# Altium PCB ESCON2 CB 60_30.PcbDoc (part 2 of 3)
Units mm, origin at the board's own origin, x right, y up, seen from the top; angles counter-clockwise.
Board outline 93.5 x 46 mm, 8 copper layers (Top Side, Inner Layer 1, Inner Layer 2, Inner Layer 3, Inner Layer 4, Inner Layer 5, Inner Layer 6, Bottom Side), stack 1.485 mm thick; 144 components, 77 nets, 473 pads, 3049 vias.
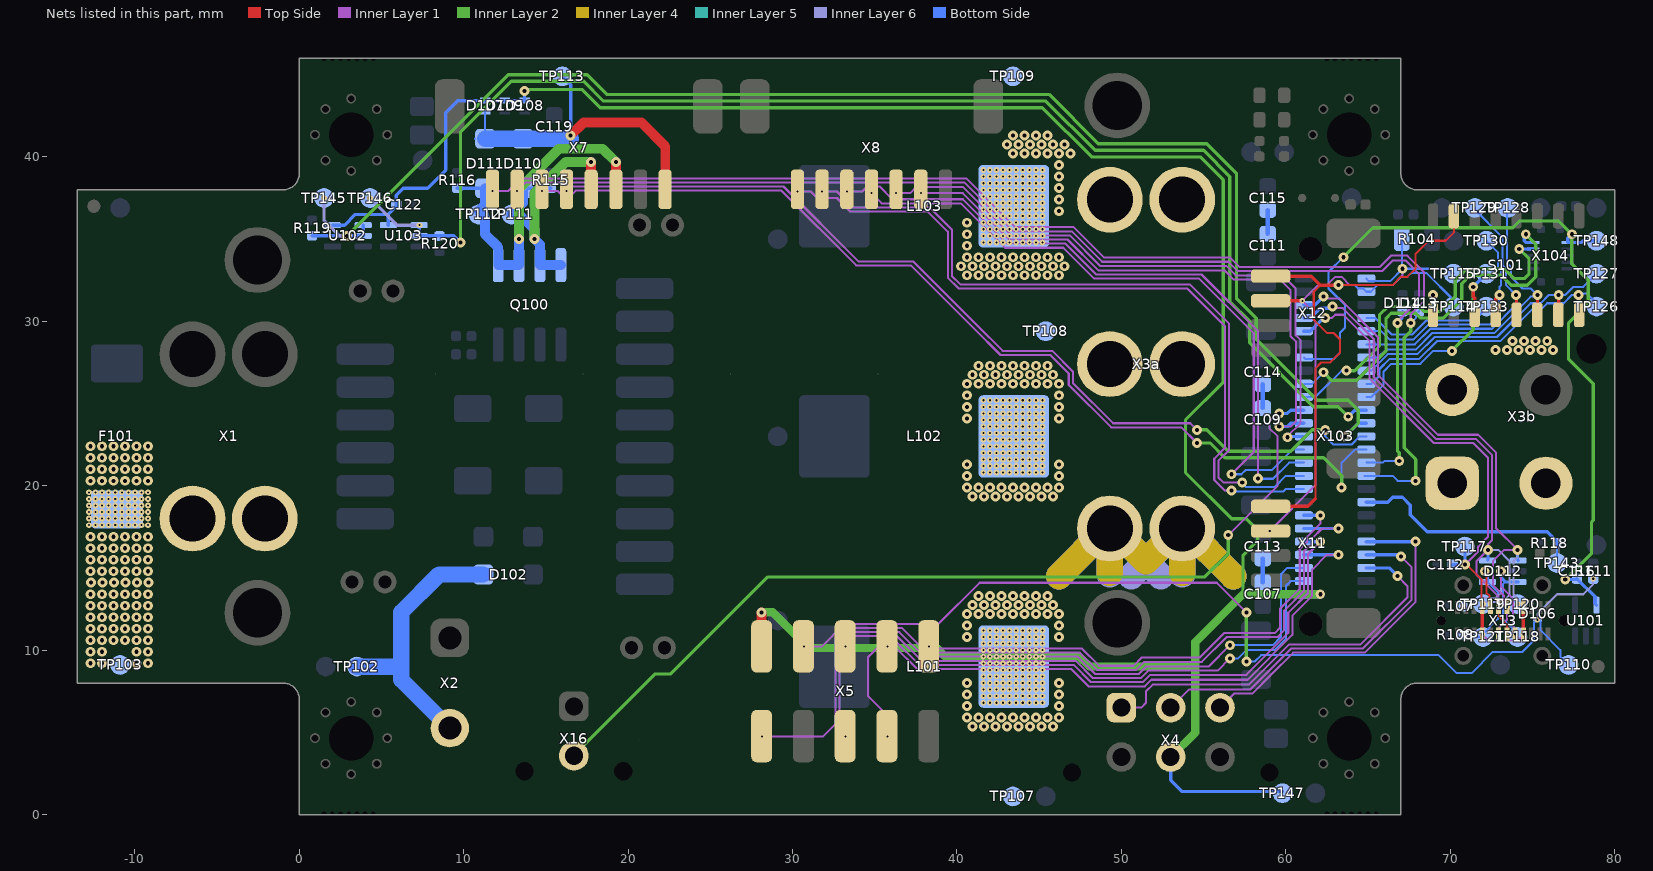
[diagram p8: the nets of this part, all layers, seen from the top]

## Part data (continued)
D112: library part CMP-000635-10, "Transient Voltage Suppressor Diode, 4-Line, 5V V(RWM), Unidirectional, 30W, 4 Element , SOT353/SC-88A", Breakdown Voltage=6.8V, Case="SOT353; SC-88A; SOT323-5L", Clamping Voltage=12V, Manufacturer=Nexperia, Max Breakdown Voltage=7.14V, Max Junction Temperature=150°C, Min Breakdown Voltage=6.46V, Min Operating Temperature=-65°C
D113 D114: library part CMP-000066-17, "Transient Voltage Suppressor Diode, 30V V(RWM), Bidirectional, ESD, 1 Element, 0402", Breakdown Voltage=30V, Case=0402, Manufacturer=Panasonic, Max Operating Temperature=125°C, Min Operating Temperature=-55°C
DS101: library part CMP-000723-6, "Single Color Chip LED, red, 0603", Case=0603, Color(s)=Red, Manufacturer=Dialight, Max Operating Temperature=100°C, Min Operating Temperature=-40°C
DS102: library part CMP-000722-5, "Single Color Chip LED, green, 0603", Case=0603, Color(s)=Green, Manufacturer=Dialight, Max Operating Temperature=100°C, Min Operating Temperature=-40°C
F101: library part CMP-001105-4, "Electric Fuse, Fast Acting, 40A, 72VDC, Surface Mount", Case=0456, Current Rating=40A, Manufacturer=BelFuse, Max Operating Temperature=125°C, Maximum Working Voltage=72V, Min Operating Temperature=-55°C
FD101 FD102 FD103 FD104: library part CMP-000010-5, "Fiducial, Global, Round; 0.80 mm D, 1.60 mm Clearance"
L101 L102 L103: library part CMP-001104-3, "Inductor Shielded, 0.47uH, 20%, I_RMS>34A, I_Sat>58A, R<1.3mOhm, 13.0x14.0mm, Height<=5mm", DC Resistance=1.3m, Max Operating Temperature=125°C, Min Operating Temperature=-55°C, RMS Current=34A, Saturation Current=58A, Tolerance=20%
LS101: library part CMP-001088-3, "Layer Stair 8 Layer"
MH101 MH102 MH103 MH104: library part CMP-000029-10, "Mounting Hole, Non-Plated; 5.50 mm Clearance, 2.70 mm Hole (with 8 vias)"
Q100: library part CMP-001108-5, "N-Channel MOSFET, Self Protected, 36V, 0.5ohm, SO-8", Case="SO-8, SOIC-8, PG-DSO-8", Drain Source Voltage=36V, Manufacturer="ST Microelectronics", Max Operating Temperature=150°C, Min Operating Temperature=-55°C
R102 R103 R105: library part CMP-000398-10, "47R 1% 250mW 100ppm", Case=1206, Case (Metric)=3216, Manufacturer=X, Max Junction Temperature=155°C, Maximum Overload Voltage=400V, Maximum Working Voltage=200V, Min Operating Temperature=-55°C, Part Number="Thick-Film, 1206, 47, 1%, 250mW@70°C, 200V, 100ppm, -55°C to 155°C", Power Rating=250mW, Power Rating Temperature=70°C, Temperature Coefficient=100ppm, Tolerance=1%
R104: library part CMP-000325-10, "120R 1% 125mW 100ppm", Case=0805, Case (Metric)=2012, Manufacturer=X, Max Junction Temperature=155°C, Maximum Overload Voltage=300V, Maximum Working Voltage=150V, Min Operating Temperature=-55°C, Part Number="Thick-Film, 0805, 120, 1%, 125mW@70°C, 150V, 100ppm, -55°C to 155°C", Power Rating=125mW, Power Rating Temperature=70°C, Temperature Coefficient=100ppm, Tolerance=1%
R107 R108: library part CMP-000206-11, "5.1k 1% 62.5mW 100ppm", Case=0402, Case (Metric)=1050, Manufacturer=X, Max Junction Temperature=155°C, Maximum Overload Voltage=100V, Maximum Working Voltage=50V, Min Operating Temperature=-55°C, Part Number="Thick-Film, 0402, 5.1k, 1%, 62.5mW@70°C, 50V, 100ppm, -55°C to 155°C", Power Rating=62.5mW, Power Rating Temperature=70°C, Temperature Coefficient=100ppm, Tolerance=1%
R109 R110: library part CMP-000185-11, "680R 1% 62.5mW 100ppm", Case=0402, Case (Metric)=1050, Manufacturer=X, Max Junction Temperature=155°C, Maximum Overload Voltage=100V, Maximum Working Voltage=50V, Min Operating Temperature=-55°C, Part Number="Thick-Film, 0402, 680, 1%, 62.5mW@70°C, 50V, 100ppm, -55°C to 155°C", Power Rating=62.5mW, Power Rating Temperature=70°C, Temperature Coefficient=100ppm, Tolerance=1%
R111: library part CMP-000161-11, "47R 1% 62.5mW 100ppm", Case=0402, Case (Metric)=1050, Manufacturer=X, Max Junction Temperature=155°C, Maximum Overload Voltage=100V, Maximum Working Voltage=50V, Min Operating Temperature=-55°C, Part Number="Thick-Film, 0402, 47, 1%, 62.5mW@70°C, 50V, 100ppm, -55°C to 155°C", Power Rating=62.5mW, Power Rating Temperature=70°C, Temperature Coefficient=100ppm, Tolerance=1%
R112 R114: library part CMP-000173-11, "220R 1% 62.5mW 100ppm", Case=0402, Case (Metric)=1050, Manufacturer=X, Max Junction Temperature=155°C, Maximum Overload Voltage=100V, Maximum Working Voltage=50V, Min Operating Temperature=-55°C, Part Number="Thick-Film, 0402, 220, 1%, 62.5mW@70°C, 50V, 100ppm, -55°C to 155°C", Power Rating=62.5mW, Power Rating Temperature=70°C, Temperature Coefficient=100ppm, Tolerance=1%
R115 R116: library part CMP-000197-11, "2.2k 1% 62.5mW 100ppm", Case=0402, Case (Metric)=1050, Manufacturer=X, Max Junction Temperature=155°C, Maximum Overload Voltage=100V, Maximum Working Voltage=50V, Min Operating Temperature=-55°C, Part Number="Thick-Film, 0402, 2.2k, 1%, 62.5mW@70°C, 50V, 100ppm, -55°C to 155°C", Power Rating=62.5mW, Power Rating Temperature=70°C, Temperature Coefficient=100ppm, Tolerance=1%
R117: library part CMP-000466-10, "0R Jumper", Case=0402, Case (Metric)=1050, Manufacturer=X, Max Junction Temperature=155°C, Maximum Overload Voltage=100V, Maximum Working Voltage=50V, Min Operating Temperature=-55°C, Part Number="Thick-Film, 0402, 0, -55°C to 155°C", RMS Current=1A
R118 R119 R120 R121: library part CMP-000492-11, "10k 1% 62.5mW 100ppm", Case=0402, Case (Metric)=1050, Manufacturer=X, Max Junction Temperature=155°C, Maximum Overload Voltage=100V, Maximum Working Voltage=50V, Min Operating Temperature=-55°C, Part Number="Thick-Film, 0402, 10k, 1%, 62.5mW@70°C, 50V, 100ppm, -55°C to 155°C", Power Rating=62.5mW, Power Rating Temperature=70°C, Temperature Coefficient=100ppm, Tolerance=1%
S101: library part CMP-001031-3, "Slide Dip Switch, 8 Switches, 0.025A, 24VDC, SMD", Manufacturer=Diptronics, Max Operating Temperature=85°C, Min Operating Temperature=-40°C
STEG101 STEG102 STEG103 STEG104: library part CMP-000007-5, "Breakaway tabs; 4.00 mm L X 0.90 mm W, 7 Hole"
SYM101: library part CMP-000019-5, "ESD-Sign; 2.5 mm L X 2.25 mm W"
SYM702: library part CMP-001187-11, "Barcode EMS; 4.1 x 4.1 mm"
TP101 TP102 TP103 TP104 TP106 TP107 TP108 TP109 TP110 TP111 TP112 TP113 TP114 TP115 TP116 TP117 TP118 TP119 TP120 TP121 TP125 TP126 TP127 TP128 TP129 TP130 TP131 TP132 TP133 TP134 TP138 TP139 TP140 TP141 TP142 TP143 TP144 TP145 TP146 TP147 TP148 TP149 TP153 TP154 TP155: library part CMP-000014-7, "Test Point; 1 pin, 1.20 mm D"
TPM1 TPM2: library part CMP-001150-4, "Test point measure; 1 pin, 0.50 mm D"
U101: library part CMP-001041-6, "Single buffer with Schmitt-Trigger inputs", Case="5-TSSOP, SC-70-5, SOT-353", Manufacturer="Texas Instruments", Max Operating Temperature=125°C, Max Storage Temperature=150°C, Max Supply Voltage=5.5V, Min Operating Temperature=-40°C, Min Storage Temperature=-65°C, Min Supply Voltage=1.65V
U102 U103: library part CMP-002037-1, "Single, 2-Input NAND Gate, 5V", Case="SC-88A , SC-70-5, SOT353-1", Max Operating Temperature=125°C, Max Supply Voltage=5.5V, Min Operating Temperature=-40°C, Min Supply Voltage=4.5V
X1: library part CMP-001093-5, "10.00mm Pitch Mini-Fit Sr. Header, Single Row, Vertical, 1.57mm PCB Thickness, 2 Circuits", Manufacturer=Molex, Max Operating Temperature=105°C, Min Operating Temperature=-40°C, Operating Current=50A, Operating Voltage=600V
X2: library part CMP-001018-5, "Mini-Fit Jr. Vertical Header, 4.20mm Pitch, Dual Row, 2 Circuits, without Snap-in Plastic Peg PCB Lock, Tin, Natural", Manufacturer=Molex, Max Operating Temperature=105°C, Min Operating Temperature=-40°C, Operating Current=9A, Operating Voltage=600V
X3a: library part CMP-001094-4, "10.00mm Pitch Mini-Fit Sr. Header, Single Row, Vertical, 1.57mm PCB Thickness, 3 Circuits", Manufacturer=Molex, Max Operating Temperature=105°C, Min Operating Temperature=-40°C, Operating Current=50A, Operating Voltage=600V
X3b: library part CMP-001095-4, "Mega-Fit Slim Vertical Header, Through Hole, 5.70mm Pitch, Dual Row, 4 Circuits, Black", Manufacturer=Molex, Max Operating Temperature=120°C, Min Operating Temperature=-40°C, Operating Current=23.5A, Operating Voltage=600V
X4: library part CMP-001098-6, "Micro-Fit 3.0 Vertical Header, 3.00mm Pitch, Dual Row, 6 Circuits, with PCB Polarizing Peg, Black", Manufacturer=Molex, Max Operating Temperature=105°C, Min Operating Temperature=-40°C, Operating Current=8.5A, Operating Voltage=600V
X5: library part CMP-001165-3, "Header, 2.54mm Pitch, Dual Row, SMT, Vertical, 10 Circuits", Manufacturer=Amphenol, Max Operating Temperature=125°C, Min Operating Temperature=-65°C, Operating Current=3A, Operating Voltage=500V
X7: library part CMP-001014-7, "1.50mm Pitch, CLIK-Mate PCB Receptacle, Single Row, Surface Mount, Tin Plating, Positive Lock, with Pick-and-Place Polyimide Tape, 8 Circuits, Beige", Manufacturer=Molex, Max Operating Temperature=105°C, Min Operating Temperature=-40°C, Operating Current=2A, Operating Voltage=100V
X8: library part CMP-001015-7, "1.50mm Pitch, CLIK-Mate PCB Receptacle, Single Row, Surface Mount, Tin Plating, Positive Lock, with Pick-and-Place Polyimide Tape, 7 Circuits, Beige", Manufacturer=Molex, Max Operating Temperature=105°C, Min Operating Temperature=-40°C, Operating Current=2A, Operating Voltage=100V
X11 X12: library part CMP-001170-6, "1.50mm Pitch, CLIK-Mate PCB Receptacle, Single Row, Surface Mount, Tin Plating, Positive Lock, with Pick-and-Place Polyimide Tape, 4 Circuits, Beige", Manufacturer=Molex, Max Operating Temperature=105°C, Min Operating Temperature=-40°C, Operating Current=2A, Operating Voltage=100V
X13: library part CMP-001110-9, "USB Type C, SHLD, 24poles, vertical", Manufacturer=GTC, Max Operating Temperature=85°C, Min Operating Temperature=-25°C
X16: library part CMP-001107-4, "Micro-Fit 3.0 Vertical Header, 3.00mm Pitch, Dual Row, 2 Circuits, with PCB Polarizing Peg, Black", Manufacturer=Molex, Max Operating Temperature=105°C, Min Operating Temperature=-40°C, Operating Current=8.5A, Operating Voltage=600V
X101: library part CMP-001100-9, "2.00 mm mPOWER® Ultramikro-Power-Socket, 6-polig", Manufacturer=Samtec, Max Operating Temperature=125°C, Min Operating Temperature=-55°C, Operating Current=18A, Operating Voltage=460V
X102: library part CMP-001189-6, "2.00 mm mPOWER® Ultramikro-Power-Socket, 10-polig", Manufacturer=Samtec, Max Operating Temperature=125°C, Min Operating Temperature=-55°C, Operating Current=18A, Operating Voltage=460V
X103: library part CMP-001102-8, "0.80 mm Edge Rate® Rugged High Speed Terminal", Max Operating Temperature=125°C, Min Operating Temperature=-55°C, Operating Current=1.4A, Operating Voltage=225V
X104: library part CMP-001083-11, "Board to Board Connector, 2*5 pole, SMD, 0.4mm pitch, 1.5mm stacking Height", Manufacturer=Panasonic, Max Operating Temperature=85°C, Min Operating Temperature=-55°C, Operating Current=300mA, Operating Voltage=60V

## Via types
v1: diameter 0.35, hole 0.125, Inner Layer 6 to Bottom Side, tented both sides, 1246 vias
v2: diameter 0.6, hole 0.25, Top Side to Bottom Side, 953 vias
v3: diameter 0.35, hole 0.125, Top Side to Inner Layer 1, tented both sides, 790 vias
v4: diameter 0.6, hole 0.25, Top Side to Bottom Side, tented bottom, 58 vias
v5: diameter 0.6, hole 0.25, Top Side to Bottom Side, tented top, 2 vias

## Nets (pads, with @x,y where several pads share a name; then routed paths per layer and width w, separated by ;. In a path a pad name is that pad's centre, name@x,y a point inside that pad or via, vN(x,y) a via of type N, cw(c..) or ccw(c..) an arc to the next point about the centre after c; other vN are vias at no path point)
3V3: C116.2 TP148.1 U101.5 X103.38 X104.1 | length 52.8
  Inner Layer 2 w0.2: v2(63.5,33.9) 65.3,35.7 73.8,35.7 74.2,36.1 76.6,36.1 v2(77.4,35.3) 77.4,33.5 78.4,32.5 78.4,31.1 77.2,29.9 77.2,27.7 78.7,26.2 78.7,17.9 78.6,17.8 78.6,15.9 v2(77,14.3)
  Bottom Side w0.125: X103.38@61.1,27.8 61.2,27.7 62.9,27.7 63.3,28.1 63.3,29.3 63.6,29.6 63.6,31 62.6,32 62.6,33 v2(63.5,33.9)
  Bottom Side w0.2: v2(77,14.3) 77.7,14.3 C116.2@77.7,14.35 78.815,13.235 78.815,12.82 U101.5@78.9,12.735 ; v2(77.4,35.3) 77.145,35.045 X104.1@77.145,34.8 78,34.8 78.1,34.9 TP148.1@78.9,34.9
5V0_sensor1_2: C122.2 D107.2 D108.2 D109.2 TP147.1 U102.5 U103.5 X4.5 X5.2 X103.2 | length 148
  Top Side w0.6: v2(28.1,12.3) 28.1,11.84 28.12,11.82 X5.2@28.12,10.23
  Inner Layer 2 w0.2: v2(13.7,44) 13.8,44.1 17.2,44.1 18.3,43 45.2,43 48.2,40 54.8,40 56.2,38.6 56.2,26.3 53.9,24 53.9,20.8 56.7,18 57.6,18 58.3,17.3 58.3,16.675 57.4,15.775 57.4,13.4
  Inner Layer 2 w0.5: v2(28.1,12.3) 28.8,12.3 30.975,10.125 38.775,10.125 39.275,9.625 47.425,9.625 48.05,9 54.497,9 ; X4.5@53,3.5 54.497,4.997 54.497,9 ; v2(62.1,13.4) 57.4,13.4 54.497,10.497 54.497,9
  Bottom Side w0.2: U102.5@2.015,35.85 2.75,35.85 3.4,36.5 5.415,36.5 ; U103.5@5.415,35.85 5.415,36.5 ; v2(13.7,44) D108.2@13.7,43.425 D109.2@12.5,43.425 D107.2@11.3,43.425 9.625,43.425 8.9,42.7 8.9,39.2 7.8,38.1 6.325,38.1 5.9,37.675 C122.2@5.9,37.1 5.9,36.985 5.415,36.5 ; X4.5@53,3.5 53,2.1 53.7,1.4 TP147.1@59.8,1.4
  Bottom Side w0.5: X103.2@61.1,13.4 v2(62.1,13.4)
C_ADC_CB_Ident: R118.2 TP143.1 X103.15 | length 14.5
  Bottom Side w0.125: TP143.1@76.5,15.3 R118.2@76.5,16.4
  Bottom Side w0.2: X103.15@64.9,19 66.2,19 66.5,19.3 67.1,19.3 67.575,18.825 67.575,18.225 68.6,17.2 75.9,17.2 76.5,16.6 R118.2@76.5,16.4
C_AnIN1+: X8.1 X103.18 | length 46.5
  Inner Layer 1 w0.125: v3(30.3,37.9) 31.1,37.9 31.5,37.5 32.7,37.5 33.525,36.675 38.225,36.675 39.45,35.45 39.45,32.65 40.1,32 54,32 56.3,29.7 56.3,22.3 55.65,21.65 55.65,20.35 56.3,19.7 v2(56.7,19.7)
  Bottom Side w0.125: v2(56.7,19.7) 56.75,19.65 59.85,19.65 60,19.8 X103.18@61.1,19.8
C_AnIN1-: X8.2 X103.20 | length 45.1
  Inner Layer 1 w0.125: v3(31.8,37.9) 32.7,37.9 33.675,36.925 38.35,36.925 39.7,35.575 39.7,32.754 40.204,32.25 54.15,32.25 56.55,29.85 56.55,22.175 55.9,21.525 55.9,20.5 56.2,20.2 v2@57.3,20.2
  Bottom Side w0.125: v2@57.3,20.2 57.575,19.925 59.325,19.925 60,20.6 X103.20@61.1,20.6
  other v2: 57.35,20.2
C_AnIN2+: X8.3 X103.22 | length 40.9
  Inner Layer 1 w0.125: v3(33.3,37.9) 34.25,37.9 34.55,38.2 35.3,38.2 36.075,37.425 40.35,37.425 43.05,34.725 46.6,34.725 48.475,32.85 54.875,32.85 58.3,29.425 v2(58.3,20.45)
  Bottom Side w0.125: v2(58.3,20.45) 58.325,20.425 59.225,20.425 60.2,21.4 X103.22@61.1,21.4
C_AnIN2-: X8.4 X103.24 | length 41
  Inner Layer 1 w0.125: v3(34.8,37.8) 35.425,37.175 40.225,37.175 42.925,34.475 46.475,34.475 48.35,32.6 54.725,32.6 58.05,29.275 58.05,22.05 v2@56.668,20.668
  Bottom Side w0.125: v2(56.7,20.7) 57.3,20.7 57.55,20.95 59.15,20.95 60.4,22.2 X103.24@61.1,22.2
C_AnOUT1: X8.5 X103.26 | length 37.5
  Inner Layer 1 w0.125: v3(36.3,37.8) 37.15,37.8 37.525,38.175 40.35,38.175 43.3,35.225 46.85,35.225 48.7,33.375 56.375,33.375 56.95,32.8 59.8,32.8 60.6,32 60.6,31.1 60.6,29.15 60.9,28.85 60.9,23.8 v2@60.1,23
  Bottom Side w0.2: v2@60.1,23 60.55,23 X103.26@61.1,23
  other v2: 60.1,22.95
C_AnOUT2: X8.6 X103.28 | length 35.8
  Inner Layer 1 w0.125: v3(37.8,37.8) 40.35,37.8 43.175,34.975 46.725,34.975 48.6,33.1 56.275,33.1 56.838,32.538 59.662,32.538 60.3,31.9 60.3,31 60.3,29.075 60.625,28.75 60.625,23.925 60.3,23.6 v2(59.6,23.6)
  Bottom Side w0.2: v2(59.6,23.6) 60.1,23.6 60.3,23.8 X103.28@61.1,23.8
C_CANH: S101.7 TP114.1 X11.1 X12.1 X103.47 | length 40.9
  Top Side w0.125: 61.8,19.2 61.8,27.125 62.175,27.5 62.7,27.5 63.3,28.1 63.3,28.9 62.9,29.3 62.5,29.3 61.7,30.1 61.7,31.8 62.1,32.2 ; v2(63.2,32.2) 64.2,32.2 65.375,32.2 66.5,32.2 67,32.7 67.4,32.7 67.9,33.2 67.9,34.1 68.7,34.9 69.725,34.9 70.225,35.4 S101.7@70.225,36.407
  Top Side w0.2: X11.1@59.025,18.75 61.35,18.75 61.8,19.2 ; X12.1@59.075,32.75 61.55,32.75 62.1,32.2 v2(63.2,32.2)
  Bottom Side w0.125: v2(63.2,32.2) 64.2,32.2 64.4,32 64.7,32 X103.47@64.9,31.8 65.175,31.8 65.575,32.2 66.5,32.2 67,32.7 67.4,32.7 67.65,32.95 68.55,32.95 70.2,31.3 TP114.1@70.2,30.9
C_CANL: R104.2 TP115.1 X11.2 X12.2 X103.49 | length 32.6
  Top Side w0.2: X12.2@59.025,31.25 X12.2@59.075,31.25 v3@61.004,31.25
  Inner Layer 1 w0.125: v3(59.025,17.25) 61.8,20.025 61.8,30 61.7,30.1 61.7,30.554 v3(61.005,31.249) 61.915,32.16 62.46,32.16 63,32.7 63.4,32.7 63.9,32.2 66.5,32.2 67.1,32.8 v2(67.1,33.2)
  Bottom Side w0.125: X103.49@64.9,32.6 65.05,32.45 66.35,32.45 v2(67.1,33.2) 69.9,33.2 TP115.1@70.2,32.9 ; v2@67.075,33.225 R104.2@67.075,35
C_DigIN1: D113.2 X7.1 X103.19 | length 77.5
  Inner Layer 1 w0.125: v3(11.75,37.925) 12.7,37.925 13.475,38.7 40.575,38.7 43.55,35.725 47.1,35.725 48.95,33.875 56.625,33.875 57.2,33.3 65.7,33.3 66.4,34 67.4,34 68.4,33 68.4,31.225 67.6,30.425 v2(67.6,29.9)
  Inner Layer 2 w0.2: v2(67.6,29.9) 67.6,29.4 67.2,29 67.2,22.3 67.9,21.6 v2(67.9,20.3)
  Bottom Side w0.125: X103.19@64.8,20.6 66.5,20.6 66.8,20.3 v2(67.9,20.3) ; v2(67.6,29.9) 67.927,30.227 67.927,30.442 D113.2@68.1,30.615
C_DigIN2: D114.2 X7.2 X103.21 | length 72.8
  Inner Layer 1 w0.125: v3(13.25,37.925) 13.775,38.45 40.45,38.45 43.425,35.475 46.975,35.475 48.825,33.625 56.5,33.625 57.075,33.05 65.85,33.05 66.5,33.7 67.3,33.7 68.1,32.9 68.1,31.3 v2@66.7,29.9
  Inner Layer 2 w0.2: v2(66.8,29.9) 66.8,22.1 66.9,22 v2(66.9,21.5)
  Bottom Side w0.125: X103.21@64.9,21.4 65.9,21.4 66,21.5 v2(66.9,21.5) ; v2(66.8,29.9) 67.1,30.2 D114.2@67.1,30.615
C_DigIN3: X7.3 X103.23 | length 60.6
  Inner Layer 1 w0.125: v3(14.75,37.925) 15.725,37.925 16.1,37.55 16.4,37.55 16.8,37.95 29.325,37.95 33.875,33.4 37.2,33.4 41,29.6 42.65,27.95 45.675,27.95 46.8,26.825 46.8,26.125 49.375,23.55 53.65,23.55 v2(54.6,22.6)
  Inner Layer 2 w0.2: v2(54.6,22.6) 55.4,22.6 56.3,21.7 62.3,21.7 63.4,20.6 v2(63.4,19.9)
  Bottom Side w0.125: v2(63.4,19.9) 63.4,21.4 64.2,22.2 X103.23@64.9,22.2
C_DigIN4: X7.4 X103.25 | length 57.2
  Inner Layer 1 w0.125: v3(16.25,37.925) 16.525,38.2 29.45,38.2 34,33.65 37.325,33.65 41.25,29.725 42.775,28.2 45.8,28.2 47.05,26.95 47.05,26.25 49.5,23.8 54.2,23.8 v2(54.6,23.4)
  Inner Layer 2 w0.2: v2(54.6,23.4) 55.2,23.4 56.5,22.1 60.3,22.1 61.6,23.4 v2(62.4,23.4)
  Bottom Side w0.125: v2(62.4,23.4) 62.4,23 62.9,22.5 64,22.5 64.5,23 X103.25@64.9,23
C_DigOUT1: D110.2 Q100.7 Q100.8 R115.1 TP111.1 X7.5 | length 17.3
  Top Side w0.6: X7.5@17.75,37.925 v2@17.75,39.6
  Inner Layer 2 w0.6: v2(14.3,35) 14.3,37.8 16.2,39.7 v2(17.75,39.7)
  Bottom Side w0.2: D110.2@13.6,38.095 14.205,38.095 14.21,38.1 R115.1@15.3,38.1
  Bottom Side w0.6: TP111.1@12.9,36.5 13.6,37.2 D110.2@13.6,38.095 ; TP111.1@13.3,36.6 14.3,35.6 v2(14.3,35) 14.635,34.665 Q100.7@14.635,33.42 Q100.8@15.905,33.42
C_DigOUT2: D111.2 Q100.5 Q100.6 R116.1 TP112.1 X7.6 | length 22.2
  Top Side w0.6: X7.6@19.25,37.925 v2@19.25,39.6
  Inner Layer 2 w0.6: v2(13.35,35) 13.35,38.05 15.8,40.5 18.45,40.5 v2(19.25,39.7)
  Bottom Side w0.2: R116.1@9.6,38.1 10.69,38.1 10.695,38.095 D111.2@11.3,38.095
  Bottom Side w0.6: TP112.1@11.205,36.7 TP112.1@10.9,36.7 ; D111.2@11.3,38.095 11.3,37.1 TP112.1@10.9,36.7 ; v2(13.35,35) 13.365,34.985 Q100.6@13.365,33.42 Q100.5@12.095,33.42 12.095,34.505 11.3,35.3 11.3,36.3 TP112.1@10.9,36.7
C_MotorTemp: X16.2 X103.30 | length 56.7
  Inner Layer 1 w0.125: v2(56.5,17) 59.5,20 59.5,23 59,23.5 59,23.9 59.5,24.4 v2(59.6,24.4)
  Inner Layer 2 w0.2: X16.2@16.7,3.6 21.65,8.55 22.6,8.55 28.5,14.45 55.075,14.45 56.5,15.875 v2(56.5,17)
  Bottom Side w0.2: v2(59.6,24.4) 60.1,24.4 60.3,24.6 X103.30@61.1,24.6
C_S1_Hall1: X4.1 X103.5 | length 24.2
  Inner Layer 1 w0.125: X4.1@50,6.5 51.2,6.5 51.5,6.8 51.5,7.5 51.9,7.9 57.75,7.9 60.2,10.35 64.55,10.35 67.4,13.2 67.4,13.9 v2(66.8,14.5)
  Bottom Side w0.2: X103.5@64.9,15 66.3,15 v2(66.8,14.5)
C_S1_Hall2: X4.2 X103.7 | length 22.4
  Inner Layer 1 w0.125: X4.2@53,6.5 54.1,7.6 57.825,7.6 60.325,10.1 64.675,10.1 67.65,13.075 67.65,15.05 v2(67,15.7)
  Bottom Side w0.2: X103.7@64.9,15.8 65.45,15.8 66.9,15.8 v2(67,15.7)
C_S1_Hall3: X4.3 X103.9 | length 21.2
  Inner Layer 1 w0.125: X4.3@56,6.5 56.85,7.35 57.95,7.35 59.1,8.5 60.45,9.85 64.8,9.85 67.9,12.95 v2(67.9,16.6)
  Bottom Side w0.2: X103.9@64.9,16.6 v2(67.9,16.6)
C_S2_/A: X5.5 X103.6 | length 40.4
  Inner Layer 1 w0.125: v3(33.224,4.758) 32.85,5.133 32.85,10.075 32.85,10.55 33.4,11.1 36.5,11.1 38,9.6 47.35,9.6 48.4,8.55 51.05,8.55 51.5,9 55.3,9 v2(56.6,10.3)
  Bottom Side w0.125: v2(56.6,10.3) 57,10.3 59.2,10.3 59.7,10.8 59.7,14.6 60.1,15 X103.6@61.1,15
C_S2_/B: X5.7 X103.10 | length 41
  Inner Layer 1 w0.125: v3(35.764,4.758) 35.764,6.036 34.575,7.225 34.575,9.55 35.625,10.6 36.2,10.6 37.7,9.1 47.1,9.1 48.15,8.05 51.3,8.05 51.75,8.5 57.6,8.5 60.15,11.05 60.15,12.275 61.35,13.475 61.35,15.85 v2(62.1,16.6)
  Bottom Side w0.2: X103.10@61.1,16.6 61.65,16.6 v2(62.1,16.6)
C_S2_A_HsDgin1: X5.6 X103.4 | length 33.7
  Inner Layer 1 w0.125: v3(33.224,10.218) 33.224,10.549 33.525,10.85 36.35,10.85 37.85,9.35 47.225,9.35 48.275,8.3 51.175,8.3 51.625,8.75 55.85,8.75 v2(56.6,9.5)
  Bottom Side w0.125: v2(56.6,9.5) 57.1,9.5 57.6,10 59.3,10 60,10.7 60,13.9 60.3,14.2 X103.4@61.1,14.2
C_S2_B_HsDgin2: X5.8 X103.8 | length 35.5
  Inner Layer 1 w0.125: v3(35.764,10.218) 36.207,10.218 37.575,8.85 46.95,8.85 48,7.8 51.425,7.8 51.825,8.2 57.675,8.2 60.4,10.925 60.4,12.1 61.6,13.3 61.6,14.9 62.5,15.8 v2(63.2,15.8)
  Bottom Side w0.2: X103.8@61.1,15.8 61.65,15.8 v2(63.2,15.8)
C_S2_Clock_HsDgout1: D106.2 R111.1 TP110.1 X5.4 | length 60.9
  Inner Layer 1 w0.125: v3(30.684,10.218) 31.768,10.218 33.15,11.6 38.875,11.6 41.375,14.1 55.8,14.1 v2(57.6,12.3)
  Inner Layer 2 w0.2: v2(57.6,9.3) v2(57.6,12.3)
  Inner Layer 6 w0.125: v1(75.301,11.842) 75.301,12.201 76.5,13.4 78.1,13.4 78.7,14 v1@78.7,14.3
  Bottom Side w0.125: v2(57.6,9.3) 58.1,9.3 58.5,9.7 69.3,9.7 70.4,8.6 71.3,8.6 72.6,9.9 74.4,9.9 75.1,10.6 75.1,11.675 D106.2@75.3,11.875 ; v1(75.301,11.842) 75.37,11.842 75.5,11.713 75.5,11.2 76.7,10 76.7,9.61 77.2,9.11 TP110.1@77.2,9.1
  other v1: 78.701,14.342
C_S2_Data_HsDgin4: X5.1 X103.12 | length 49.8
  Inner Layer 1 w0.125: v3(28.144,4.758) 31.858,4.758 32.6,5.5 32.6,10.675 33.275,11.35 36.65,11.35 38.15,9.85 47.475,9.85 48.525,8.8 50.9,8.8 51.387,9.287 54.888,9.287 56.4,10.8 59.5,10.8 59.9,11.2 59.9,12.4 61.1,13.6 61.1,16 61.6,16.5 61.6,16.8 62.2,17.4 v2(63.2,17.4)
  Bottom Side w0.2: X103.12@61.1,17.4 v2(63.2,17.4)
C_S2_I_HsDgin3: X5.10 X103.14 | length 31.6
  Inner Layer 1 w0.125: v3(38.304,10.218) 38.782,10.218 38.9,10.1 47.6,10.1 48.65,9.05 50.75,9.05 51.25,9.55 54.775,9.55 56.275,11.05 59.35,11.05 59.65,11.35 59.65,12.525 60.85,13.725 60.85,16.15 61.3,16.6 61.3,16.9 62.1,17.7 v2(62.1,18.2)
  Bottom Side w0.2: X103.14@61.1,18.2 61.65,18.2 v2(62.1,18.2)
C_USB_CC1: D112.3 R107.1 TP118.1 X13.A5 | length 13.5
  Inner Layer 1 w0.125: v2(73.1,14.8) 73.1,13.85 73.825,13.125 73.825,11.45 73.95,11.325 v3(73.95,10.965)
  Inner Layer 6 w0.125: v1(70.77,12.6) 71.2,12.6 71.775,13.175 72.775,13.175 73.1,13.5 v2(73.1,14.8)
  Bottom Side w0.125: 73.35,14.15 73.2,14 73.2,11.9 74.1,11 TP118.1@74.1,10.8
  Bottom Side w0.2: v2(73.1,14.8) 73.1,14.4 73.35,14.15 D112.3@74.135,14.15
C_USB_CC2: D112.4 R108.1 TP121.1 X13.B5 | length 8.3
  Top Side w0.125: v2(72.1,14.8) 72.2,14.7 72.2,13.5 72.4,13.3 72.4,12.685 X13.B5@72.45,12.635
  Bottom Side w0.125: R108.1@70.77,11 71.065,11 71.265,10.8 TP121.1@72,10.8 72,11 72.9,11.9 72.9,13.515 D112.4@72.265,14.15
  Bottom Side w0.2: v2(72.1,14.8) 72.265,14.635 D112.4@72.265,14.15
C_USB_D+: D112.5 TP119.1 X13.A6 X13.B6 X103.44 | length 34.9
  Top Side w0.125: v3(72.95,12.635) 72.95,12.05 73.45,11.55 X13.A6@73.45,10.965
  Inner Layer 1 w0.125: v2@62.8,30.8 63.475,30.8 65.35,28.925 65.35,26.625 69.125,22.85 71.55,22.85 72.55,21.85 72.55,16.7 72.3,16.45 v2(72.3,16.1) 71.6,15.4 71.6,14.6 72.95,13.25 v3(72.95,12.635)
  Inner Layer 6 w0.125: v1(72,12.8) 72.125,12.925 73.175,12.925 73.6,13.35 73.6,15.425 72.925,16.1 v2(72.3,16.1)
  Bottom Side w0.125: D112.5@72.265,15.45 D112.5@72.3,15.485
  Bottom Side w0.2: X103.44@61.1,30.2 61.5,30.2 62.1,30.8 v2@62.8,30.8 ; D112.5@72.3,15.485 v2(72.3,16.1)
  other v2: 62.85,30.9
C_USB_D-: D112.1 TP120.1 X13.A7 X13.B7 X103.46 | length 34.5
  Inner Layer 1 w0.125: v2@62.3,31.4 63.25,31.4 65.6,29.05 65.6,26.75 69.25,23.1 71.7,23.1 72.8,22 72.8,17.4 v2(74.1,16.1) 73.3,16.1 72.6,15.4 72.6,13.975 73.275,13.3 73.275,12.81 v3(73.45,12.635) 73.45,11.85 72.95,11.35 v3(72.95,10.965)
  Inner Layer 6 w0.125: v1(74.1,12.8) 74.1,13.15 73.85,13.4 73.85,15.425 74.1,15.675 v2(74.1,16.1)
  Bottom Side w0.2: X103.46@61.1,31 61.8,31 62.2,31.4 v2@62.3,31.4 ; v2(74.1,16.1) 74.1,15.485 D112.1@74.135,15.45
  other v2: 62.3,31.5
C_USB_VBUS: C112.2 TP117.1 X13.A4 X13.A9 X13.B4 X13.B9 X103.42 | length 34.7
  Top Side w0.125: v2(70.9,15.2) 71,15.2 71.9,14.3 71.9,12.685 X13.B4@71.95,12.635
  Top Side w0.2: v3(71.95,10.965) X13.B4@71.95,12.635 ; v3(74.45,10.965) X13.B9@74.45,12.635
  Inner Layer 1 w0.125: v2(62.4,30.2) 62.8,30.2 63,30.4 63.5,30.4 65.1,28.8 65.1,26.5 69,22.6 71.4,22.6 72.3,21.7 72.3,16.9 71.7,16.3 71.7,16 v2(70.9,15.2) ; v3(71.95,10.965) 72.315,10.6 74.15,10.6 74.45,10.9 v3(74.45,10.965)
  Bottom Side w0.2: X103.42@61.1,29.4 61.5,29.4 62.2,30.1 v2@62.4,30.1 ; C112.2@70.15,15.2 v2(70.9,15.2) TP117.1@70.9,16.3
C_VDigIO: C119.2 D107.1 D110.1 D111.1 TP113.1 X7.8 | length 20.3
  Top Side w0.59: X7.8@22.25,37.8 22.25,37.925 22.25,40.65
  Top Side w0.6: v2(16.5,41.3) 17.3,42.1 20.8,42.1 22.25,40.65
  Bottom Side w0.125: 10.69,41.1 D111.1@10.695,41.105 ; D111.1@11.3,41.105 D107.1@11.3,42.775
  Bottom Side w0.2: TP113.1@16,44.9 16.5,44.4 v2@16.5,41.2
  Bottom Side w1: D111.1@11.3,41.105 D110.1@13.6,41.105 15.5,41.105 15.505,41.1 v2@16.5,41.1
C_VL: D102.2 TP102.1 X2.2 | length 16.9
  Bottom Side w1: TP102.1@3.5,9 6.2,9 ; X2.2@9.15,5.25 6.2,8.2 6.2,9 ; D102.2@11.195,14.6 8.5,14.6 6.2,12.3 6.2,9
C_VP: F101.1 TP103.1 X1.2
  other v1: -12.8,17.6 -12.4,17.6 -12,17.6 -11.6,17.6 -11.2,17.6 -10.8,17.6 -10.4,17.6 -10,17.6 -9.6,17.6 -9.2,17.6 -12.8,18 -12.4,18 -12,18 -11.6,18 -11.2,18 -10.8,18 -10.4,18 -10,18 -9.6,18 -9.2,18 -12.8,18.4 -12.4,18.4 -12,18.4 -11.6,18.4 -11.2,18.4 -10.8,18.4 -10.4,18.4 -10,18.4 -9.6,18.4 -9.2,18.4 -12.8,18.8 -12.4,18.8 -12,18.8 -11.6,18.8 -11.2,18.8 -10.8,18.8 -10.4,18.8 -10,18.8 -9.6,18.8 -9.2,18.8 -12.8,19.2 -12.4,19.2 -12,19.2 -11.6,19.2 -11.2,19.2 -10.8,19.2 -10.4,19.2 -10,19.2 -9.6,19.2 -9.2,19.2 -12.8,19.6 -12.4,19.6 -12,19.6 -11.6,19.6 -11.2,19.6 -10.8,19.6 -10.4,19.6 -10,19.6 -9.6,19.6 -9.2,19.6
  other v2: -12.7,9.2 -12,9.2 -9.9,9.2 -9.2,9.2 -12.7,9.9 -12,9.9 -9.9,9.9 -9.2,9.9 -12.7,10.6 -12,10.6 -11.3,10.6 -10.6,10.6 -9.9,10.6 -9.2,10.6 -12.7,11.3 -12,11.3 -11.3,11.3 -10.6,11.3 -9.9,11.3 -9.2,11.3 -12.7,12 -12,12 -11.3,12 -10.6,12 -9.9,12 -9.2,12 -12.7,12.7 -12,12.7 -11.3,12.7 -10.6,12.7 -9.9,12.7 -9.2,12.7 -12.7,13.4 -12,13.4 -11.3,13.4 -10.6,13.4 -9.9,13.4 -9.2,13.4 -12.68,14.104 -11.98,14.104 -11.28,14.104 -10.58,14.104 -9.88,14.104 -9.18,14.104 -12.7,14.8 -12,14.8 -11.3,14.8 -10.6,14.8 -9.9,14.8 -9.2,14.8 -12.7,15.5 -12,15.5 -11.3,15.5 -10.6,15.5 -9.9,15.5 -9.2,15.5 -12.7,16.2 -12,16.2 -11.3,16.2 -10.6,16.2 -9.9,16.2 -9.2,16.2 -12.7,16.9 -12,16.9 -11.3,16.9 -10.6,16.9 -9.9,16.9 -9.2,16.9 -12.7,20.3 -12,20.3 -11.3,20.3 -10.6,20.3 -9.9,20.3 -9.2,20.3 -12.7,21 -12,21 -11.3,21 -10.6,21 -9.9,21 -9.2,21 -12.7,21.7 -12,21.7 -11.3,21.7 -10.6,21.7 -9.9,21.7 -9.2,21.7 -12.7,22.4 -12,22.4 -11.3,22.4 -10.6,22.4 -9.9,22.4 -9.2,22.4
C_W1: C107.2 C113.2 L101.1 TP107.1 X3a.1 X3b.1 | length 100.5
  Inner Layer 6 w1.6: 49.3,14.6 X3a.1@49.3,17.4 49.3,14.7 ; 50.6,14.5 53.499,17.399 51.5,15.4 49.5,17.4 52.399,14.501 ; 53.7,14.6 X3a.1@53.7,17.4 53.7,14.7 ; 46.2,14.5 49.1,17.4 46.2,14.5 ; X3a.1@53.9,17.4 56.799,14.501 X3a.1@53.9,17.4
  Inner Layer 4 w1.6: 46.2,14.5 X3a.1@49.1,17.4 ; 49.3,14.7 X3a.1@49.3,17.4 ; X3a.1@49.5,17.4 51.5,15.4 X3a.1@53.499,17.399 ; 53.7,14.7 X3a.1@53.7,17.4 ; X3a.1@53.9,17.4 56.799,14.501
  Inner Layer 5 w1.6: 46.2,14.5 X3a.1@49.1,17.4 ; 49.3,14.7 X3a.1@49.3,17.4 ; X3a.1@49.5,17.4 51.5,15.4 X3a.1@53.499,17.399 ; 53.7,14.7 X3a.1@53.7,17.4 ; X3a.1@53.9,17.4 56.799,14.501
  Bottom Side w0.25: C107.2@58.6,14.125 C113.2@58.6,15.575 C113.2@58.6,15.58
  Bottom Side w1.6: 46.2,14.5 X3a.1@49.1,17.4 ; 49.3,14.7 X3a.1@49.3,17.4 ; X3a.1@49.5,17.4 51.5,15.4 X3a.1@53.499,17.399 ; 53.7,14.7 X3a.1@53.7,17.4 ; X3a.1@53.9,17.4 56.799,14.501
  other v1: 41.6,6.8 42,6.8 42.4,6.8 42.8,6.8 43.2,6.8 43.6,6.8 44,6.8 44.4,6.8 44.8,6.8 45.2,6.8 41.6,7.2 42,7.2 42.4,7.2 42.8,7.2 43.2,7.2 43.6,7.2 44,7.2 44.4,7.2 44.8,7.2 45.2,7.2 41.6,7.6 42,7.6 42.4,7.6 42.8,7.6 43.2,7.6 43.6,7.6 44,7.6 44.4,7.6 44.8,7.6 45.2,7.6 41.6,8 42,8 42.4,8 42.8,8 43.2,8 43.6,8 44,8 44.4,8 44.8,8 45.2,8 41.6,8.4 42,8.4 42.4,8.4 42.8,8.4 43.2,8.4 43.6,8.4 44,8.4 44.4,8.4 44.8,8.4 45.2,8.4 41.6,8.8 42,8.8 42.4,8.8 42.8,8.8 43.2,8.8 43.6,8.8 44,8.8 44.4,8.8 44.8,8.8 45.2,8.8 41.6,9.2 42,9.2 42.4,9.2 42.8,9.2 43.2,9.2 43.6,9.2 44,9.2 44.4,9.2 44.8,9.2 45.2,9.2 41.6,9.6 42,9.6 42.4,9.6 42.8,9.6 43.2,9.6 43.6,9.6 44,9.6 44.4,9.6 44.8,9.6 45.2,9.6 41.6,10 42,10 42.4,10 42.8,10 43.2,10 43.6,10 44,10 44.4,10 44.8,10 45.2,10 41.6,10.4 42,10.4 42.4,10.4 42.8,10.4 43.2,10.4 43.6,10.4 44,10.4 44.4,10.4 44.8,10.4 45.2,10.4 41.6,10.8 42,10.8 42.4,10.8 42.8,10.8 43.2,10.8 43.6,10.8 44,10.8 44.4,10.8 44.8,10.8 45.2,10.8 41.6,11.2 42,11.2 42.4,11.2 42.8,11.2 43.2,11.2 43.6,11.2 44,11.2 44.4,11.2 44.8,11.2 45.2,11.2
  other v2: 40.95,5.35 41.65,5.35 42.35,5.35 43.05,5.35 43.75,5.35 44.45,5.35 45.15,5.35 45.85,5.35 40.6,5.9 41.3,5.9 42,5.9 42.7,5.9 43.4,5.9 44.1,5.9 44.8,5.9 45.5,5.9 46.2,5.9 40.6,6.6 46.2,6.6 40.6,7.3 46.2,7.3 40.6,8 46.2,8 40.6,10.8 46.2,10.8 40.6,11.5 46.2,11.5 40.6,12.2 41.3,12.2 42,12.2 42.7,12.2 43.4,12.2 44.1,12.2 44.8,12.2 45.5,12.2 46.2,12.2 40.95,12.75 41.65,12.75 42.35,12.75 43.05,12.75 43.75,12.75 44.45,12.75 45.15,12.75 45.85,12.75 41.3,13.3 42,13.3 42.7,13.3 43.4,13.3 44.1,13.3 44.8,13.3 45.5,13.3
C_W2: C109.2 C114.2 L102.1 TP108.1 X3a.2 X3b.2 | length 1.4
  Bottom Side w0.25: C109.2@58.6,24.725 C114.2@58.6,26.175
  other v1: 41.6,20.8 42,20.8 42.4,20.8 42.8,20.8 43.2,20.8 43.6,20.8 44,20.8 44.4,20.8 44.8,20.8 45.2,20.8 41.6,21.2 42,21.2 42.4,21.2 42.8,21.2 43.2,21.2 43.6,21.2 44,21.2 44.4,21.2 44.8,21.2 45.2,21.2 41.6,21.6 42,21.6 42.4,21.6 42.8,21.6 43.2,21.6 43.6,21.6 44,21.6 44.4,21.6 44.8,21.6 45.2,21.6 41.6,22 42,22 42.4,22 42.8,22 43.2,22 43.6,22 44,22 44.4,22 44.8,22 45.2,22 41.6,22.4 42,22.4 42.4,22.4 42.8,22.4 43.2,22.4 43.6,22.4 44,22.4 44.4,22.4 44.8,22.4 45.2,22.4 41.6,22.8 42,22.8 42.4,22.8 42.8,22.8 43.2,22.8 43.6,22.8 44,22.8 44.4,22.8 44.8,22.8 45.2,22.8 41.6,23.2 42,23.2 42.4,23.2 42.8,23.2 43.2,23.2 43.6,23.2 44,23.2 44.4,23.2 44.8,23.2 45.2,23.2 41.6,23.6 42,23.6 42.4,23.6 42.8,23.6 43.2,23.6 43.6,23.6 44,23.6 44.4,23.6 44.8,23.6 45.2,23.6 41.6,24 42,24 42.4,24 42.8,24 43.2,24 43.6,24 44,24 44.4,24 44.8,24 45.2,24 41.6,24.4 42,24.4 42.4,24.4 42.8,24.4 43.2,24.4 43.6,24.4 44,24.4 44.4,24.4 44.8,24.4 45.2,24.4 41.6,24.8 42,24.8 42.4,24.8 42.8,24.8 43.2,24.8 43.6,24.8 44,24.8 44.4,24.8 44.8,24.8 45.2,24.8 41.6,25.2 42,25.2 42.4,25.2 42.8,25.2 43.2,25.2 43.6,25.2 44,25.2 44.4,25.2 44.8,25.2 45.2,25.2
  other v2: 40.95,19.35 41.65,19.35 42.35,19.35 43.05,19.35 43.75,19.35 44.45,19.35 45.15,19.35 45.85,19.35 40.6,19.9 41.3,19.9 42,19.9 42.7,19.9 43.4,19.9 44.1,19.9 44.8,19.9 45.5,19.9 46.2,19.9 40.6,20.6 46.2,20.6 40.6,21.3 46.2,21.3 40.6,24.1 46.2,24.1 40.6,24.8 46.2,24.8 40.6,25.5 46.2,25.5 40.6,26.2 41.3,26.2 42,26.2 42.7,26.2 43.4,26.2 44.1,26.2 44.8,26.2 45.5,26.2 46.2,26.2 40.95,26.75 41.65,26.75 42.35,26.75 43.05,26.75 43.75,26.75 44.45,26.75 45.15,26.75 45.85,26.75 41.3,27.3 42,27.3 42.7,27.3 43.4,27.3 44.1,27.3 44.8,27.3 45.5,27.3
C_W3: C111.2 C115.2 L103.1 TP109.1 X3a.3 X3b.3 | length 1.5
  Bottom Side w0.25: C111.2@58.9,35.325 C115.2@58.9,36.775
  other v1: 41.6,34.8 42,34.8 42.4,34.8 42.8,34.8 43.2,34.8 43.6,34.8 44,34.8 44.4,34.8 44.8,34.8 45.2,34.8 41.6,35.2 42,35.2 42.4,35.2 42.8,35.2 43.2,35.2 43.6,35.2 44,35.2 44.4,35.2 44.8,35.2 45.2,35.2 41.6,35.6 42,35.6 42.4,35.6 42.8,35.6 43.2,35.6 43.6,35.6 44,35.6 44.4,35.6 44.8,35.6 45.2,35.6 41.6,36 42,36 42.4,36 42.8,36 43.2,36 43.6,36 44,36 44.4,36 44.8,36 45.2,36 41.6,36.4 42,36.4 42.4,36.4 42.8,36.4 43.2,36.4 43.6,36.4 44,36.4 44.4,36.4 44.8,36.4 45.2,36.4 41.6,36.8 42,36.8 42.4,36.8 42.8,36.8 43.2,36.8 43.6,36.8 44,36.8 44.4,36.8 44.8,36.8 45.2,36.8 41.6,37.2 42,37.2 42.4,37.2 42.8,37.2 43.2,37.2 43.6,37.2 44,37.2 44.4,37.2 44.8,37.2 45.2,37.2 41.6,37.6 42,37.6 42.4,37.6 42.8,37.6 43.2,37.6 43.6,37.6 44,37.6 44.4,37.6 44.8,37.6 45.2,37.6 41.6,38 42,38 42.4,38 42.8,38 43.2,38 43.6,38 44,38 44.4,38 44.8,38 45.2,38 41.6,38.4 42,38.4 42.4,38.4 42.8,38.4 43.2,38.4 43.6,38.4 44,38.4 44.4,38.4 44.8,38.4 45.2,38.4 41.6,38.8 42,38.8 42.4,38.8 42.8,38.8 43.2,38.8 43.6,38.8 44,38.8 44.4,38.8 44.8,38.8 45.2,38.8 41.6,39.2 42,39.2 42.4,39.2 42.8,39.2 43.2,39.2 43.6,39.2 44,39.2 44.4,39.2 44.8,39.2 45.2,39.2
  other v2: 72.75,28.25 73.45,28.25 74.15,28.25 74.85,28.25 75.55,28.25 76.25,28.25 73.8,28.8 74.5,28.8 75.2,28.8 75.9,28.8 40.6,32.8 41.3,32.8 42,32.8 42.7,32.8 43.4,32.8 44.1,32.8 44.8,32.8 45.5,32.8 46.2,32.8 40.25,33.35 40.95,33.35 41.65,33.35 42.35,33.35 43.05,33.35 43.75,33.35 44.45,33.35 45.15,33.35 45.85,33.35 46.55,33.35 40.6,33.9 41.3,33.9 42,33.9 42.7,33.9 43.4,33.9 44.1,33.9 44.8,33.9 45.5,33.9 46.2,33.9 40.6,34.6 40.6,35.3 40.6,36 46.2,36.7 46.2,37.4 46.2,38.1 46.2,38.8 46.2,39.5 43.4,40.2 44.1,40.2 44.8,40.2 45.5,40.2 46.2,40.2 46.9,40.2 43.05,40.75 43.75,40.75 44.45,40.75 45.15,40.75 45.85,40.75 46.55,40.75 43.4,41.3 44.1,41.3 44.8,41.3 45.5,41.3
CAN_AutoBR: S101.11 TP131.1 X103.31 | length 14.2
  Top Side w0.2: v2(71.4,32.1) 71.4,31.5 71.5,31.4 71.495,31.395 S101.11@71.495,30.393
  Inner Layer 2 w0.2: v2(70.1,28.2) 71.4,29.5 v2(71.4,32.1)
  Bottom Side w0.125: X103.31@64.9,25.4 65.2,25.4 65.95,26.15 65.95,26.95 66.413,27.413 68.187,27.413 68.975,28.2 v2(70.1,28.2)
  Bottom Side w0.2: v2(71.4,32.1) 72.1,32.8 72.2,32.8 TP131.1@72.2,32.9
CAN_ID1: S101.16 TP126.1 X103.33 | length 18.2
  Top Side w0.2: v2(77.8,31.6) 77.845,31.555 S101.16@77.845,30.393
  Bottom Side w0.125: X103.33@64.9,26.2 65.2,26.2 65.7,26.7 65.7,27.1 66.3,27.7 68.1,27.7 69.2,28.8 73.05,28.8 75.05,30.8 75.6,30.8 75.9,31.1 76.1,31.1 76.9,31.1 77.4,31.6 v2(77.8,31.6) 77.9,31.7 78.3,31.7 78.9,31.1 TP126.1@78.9,30.9
CAN_ID2: S101.15 TP127.1 X103.35 | length 17.7
  Top Side w0.2: S101.15@76.575,30.393 76.575,31.143 76.6,31.168 v2(76.6,31.6)
  Bottom Side w0.125: X103.35@64.9,27 65.2,27 66.2,28 68,28 69.05,29.05 72.85,29.05 74.9,31.1 75.5,31.1 76,31.6 v2(76.6,31.6) 77,31.6 77.5,32.1 78.1,32.1 TP127.1@78.9,32.9
CAN_ID3: S101.14 TP128.1 X103.37 | length 19.6
  Top Side w0.2: v2(75.3,31.6) 75.305,31.595 S101.14@75.305,30.393
  Bottom Side w0.125: X103.37@64.9,27.8 65.6,27.8 66.1,28.3 67.925,28.3 68.925,29.3 72.7,29.3 74.9,31.5 75.2,31.5 v2(75.3,31.6) 74.9,32 74.4,32 73.7,32.7 73.7,33.3 73.45,33.55 73.45,35.75 73.45,36.85 TP128.1@73.5,36.9
CAN_ID4: S101.13 TP129.1 X103.39 | length 18.3
  Top Side w0.2: v2(74,31.6) 74.035,31.565 S101.13@74.035,30.393
  Bottom Side w0.125: X103.39@64.9,28.6 67.85,28.6 68.8,29.55 72.55,29.55 74.035,31.035 74.035,31.565 v2(74,31.6) 73.4,32.2 73.4,33.2 73.175,33.425 73.175,35.125 71.5,36.8 TP129.1@71.5,36.9
CAN_ID5: S101.12 TP130.1 X103.41 | length 15.1
  Top Side w0.2: S101.12@72.765,30.393 72.765,31.365 v2(73,31.6)
  Bottom Side w0.125: X103.41@64.9,29.4 65.8,29.4 66.3,28.9 67.775,28.9 68.675,29.8 72.401,29.8 73,30.399 v2(73,31.6) 73,32.1 73.1,32.2 73.1,33.125 72.9,33.325 72.9,34.2 TP130.1@72.2,34.9
CAN_ID6: S101.9 TP133.1 X103.43 | length 12.1
  Top Side w0.15: v2@68.9,31.6 v2@68.955,31.545
  Top Side w0.2: S101.9@68.955,30.393 v2@68.955,31.545
  Bottom Side w0.125: X103.43@64.9,30.2 65.45,30.2 66.45,29.2 67.7,29.2 68.55,30.05 ; 68.95,30.1 68.95,30.25 v2(68.95,31.6) ; TP133.1@72.2,30.9 72.2,30.8 71.45,30.05 68.95,30.05 ; 68.55,30.05 68.6,30.05 68.95,30.05 ; 68.55,30.05 68.95,30.05
  Bottom Side w0.15: 69.025,30.15 ccw(c68.95,30.15) 69.025,30.15
DBG_SWCLK: X103.32 X104.4 | length 21.9
  Inner Layer 2 w0.2: v2(63.7,27) 64.2,27 65.7,28.5 65.7,30.4 66.2,30.9 68.1,30.9 68.4,30.6 69.4,30.6 70.3,31.5 70.3,32.5 71,33.2 73.3,33.2 73.9,32.6 74.5,32.6 74.8,32.9 74.8,33.8 v2(74.2,34.4)
  Bottom Side w0.125: X103.32@61.1,25.4 61.8,25.4 63.4,27 v2(63.7,27)
  Bottom Side w0.2: v2(74.2,34.4) 74.67,34.4 X104.4@75.055,34.4
DBG_SWDIO: X103.34 X104.2 | length 23.6
  Inner Layer 2 w0.2: v2(62.3,26.9) 62.8,26.4 64.3,26.4 66.1,28.2 66.1,30.2 66.4,30.5 67.9,30.5 68.2,30.2 69.575,30.2 70.7,31.325 70.7,32.3 71.2,32.8 73.1,32.8 73.7,32.2 74.7,32.2 75.2,32.7 75.2,34.7 v2(74.6,35.3)
  Bottom Side w0.125: X103.34@61.1,26.2 61.6,26.2 v2(62.3,26.9)
  Bottom Side w0.2: v2(74.6,35.3) 74.5,35.2 74.5,34.9 74.6,34.8 X104.2@75.055,34.8
DigOUT1: R119.2 TP145.1 U102.1 U102.2 X103.27 | length 89.7
  Inner Layer 2 w0.2: v2(2.9,35.2) 12.7,45 17.5,45 18.7,43.8 45.6,43.8 48.6,40.8 55.2,40.8 57,39 57,31.4 58.2,30.2 58.2,28.9 61.9,25.2 63.8,25.2 64.4,24.6 64.4,23.8 v2(63.6,23)
  Inner Layer 6 w0.2: v1(1.5,37.5) 1.5,36.125 2.425,35.2 v2(2.9,35.2)
  Bottom Side w0.2: R119.2@0.775,35.2 v2(2.9,35.2) 3.365,35.2 U102.2@3.885,35.2 U102.1@3.885,35.85 ; v2(63.6,23) 64.4,23.8 X103.27@64.9,23.8
DigOUT2: R120.2 TP146.1 U103.1 U103.2 X103.29 | length 83.9
  Inner Layer 2 w0.2: v2(9.8,34.8) 9.8,41.5 12.9,44.6 17.3,44.6 18.5,43.4 45.4,43.4 48.4,40.4 55,40.4 56.6,38.8 56.6,31.2 57.8,30 57.8,28.7 61.5,25 61.7,24.8 63.2,24.8 v2(63.8,24.2)
  Inner Layer 6 w0.2: v1(4.3,37.5) 5.95,35.85 v1(7.309,35.85)
  Bottom Side w0.2: U103.1@7.285,35.85 U103.2@7.285,35.2 8.1,35.2 9.4,35.2 v2(9.8,34.8) ; v2(63.8,24.2) 64.2,24.6 X103.29@64.9,24.6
